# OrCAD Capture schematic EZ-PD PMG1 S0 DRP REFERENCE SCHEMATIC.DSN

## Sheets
1 05. SC8802 REGULATOR: size A3; title: PMG1-S0 DRP REFERENCE DESIGN; rev: 01; note: 630-XXXXX-XX
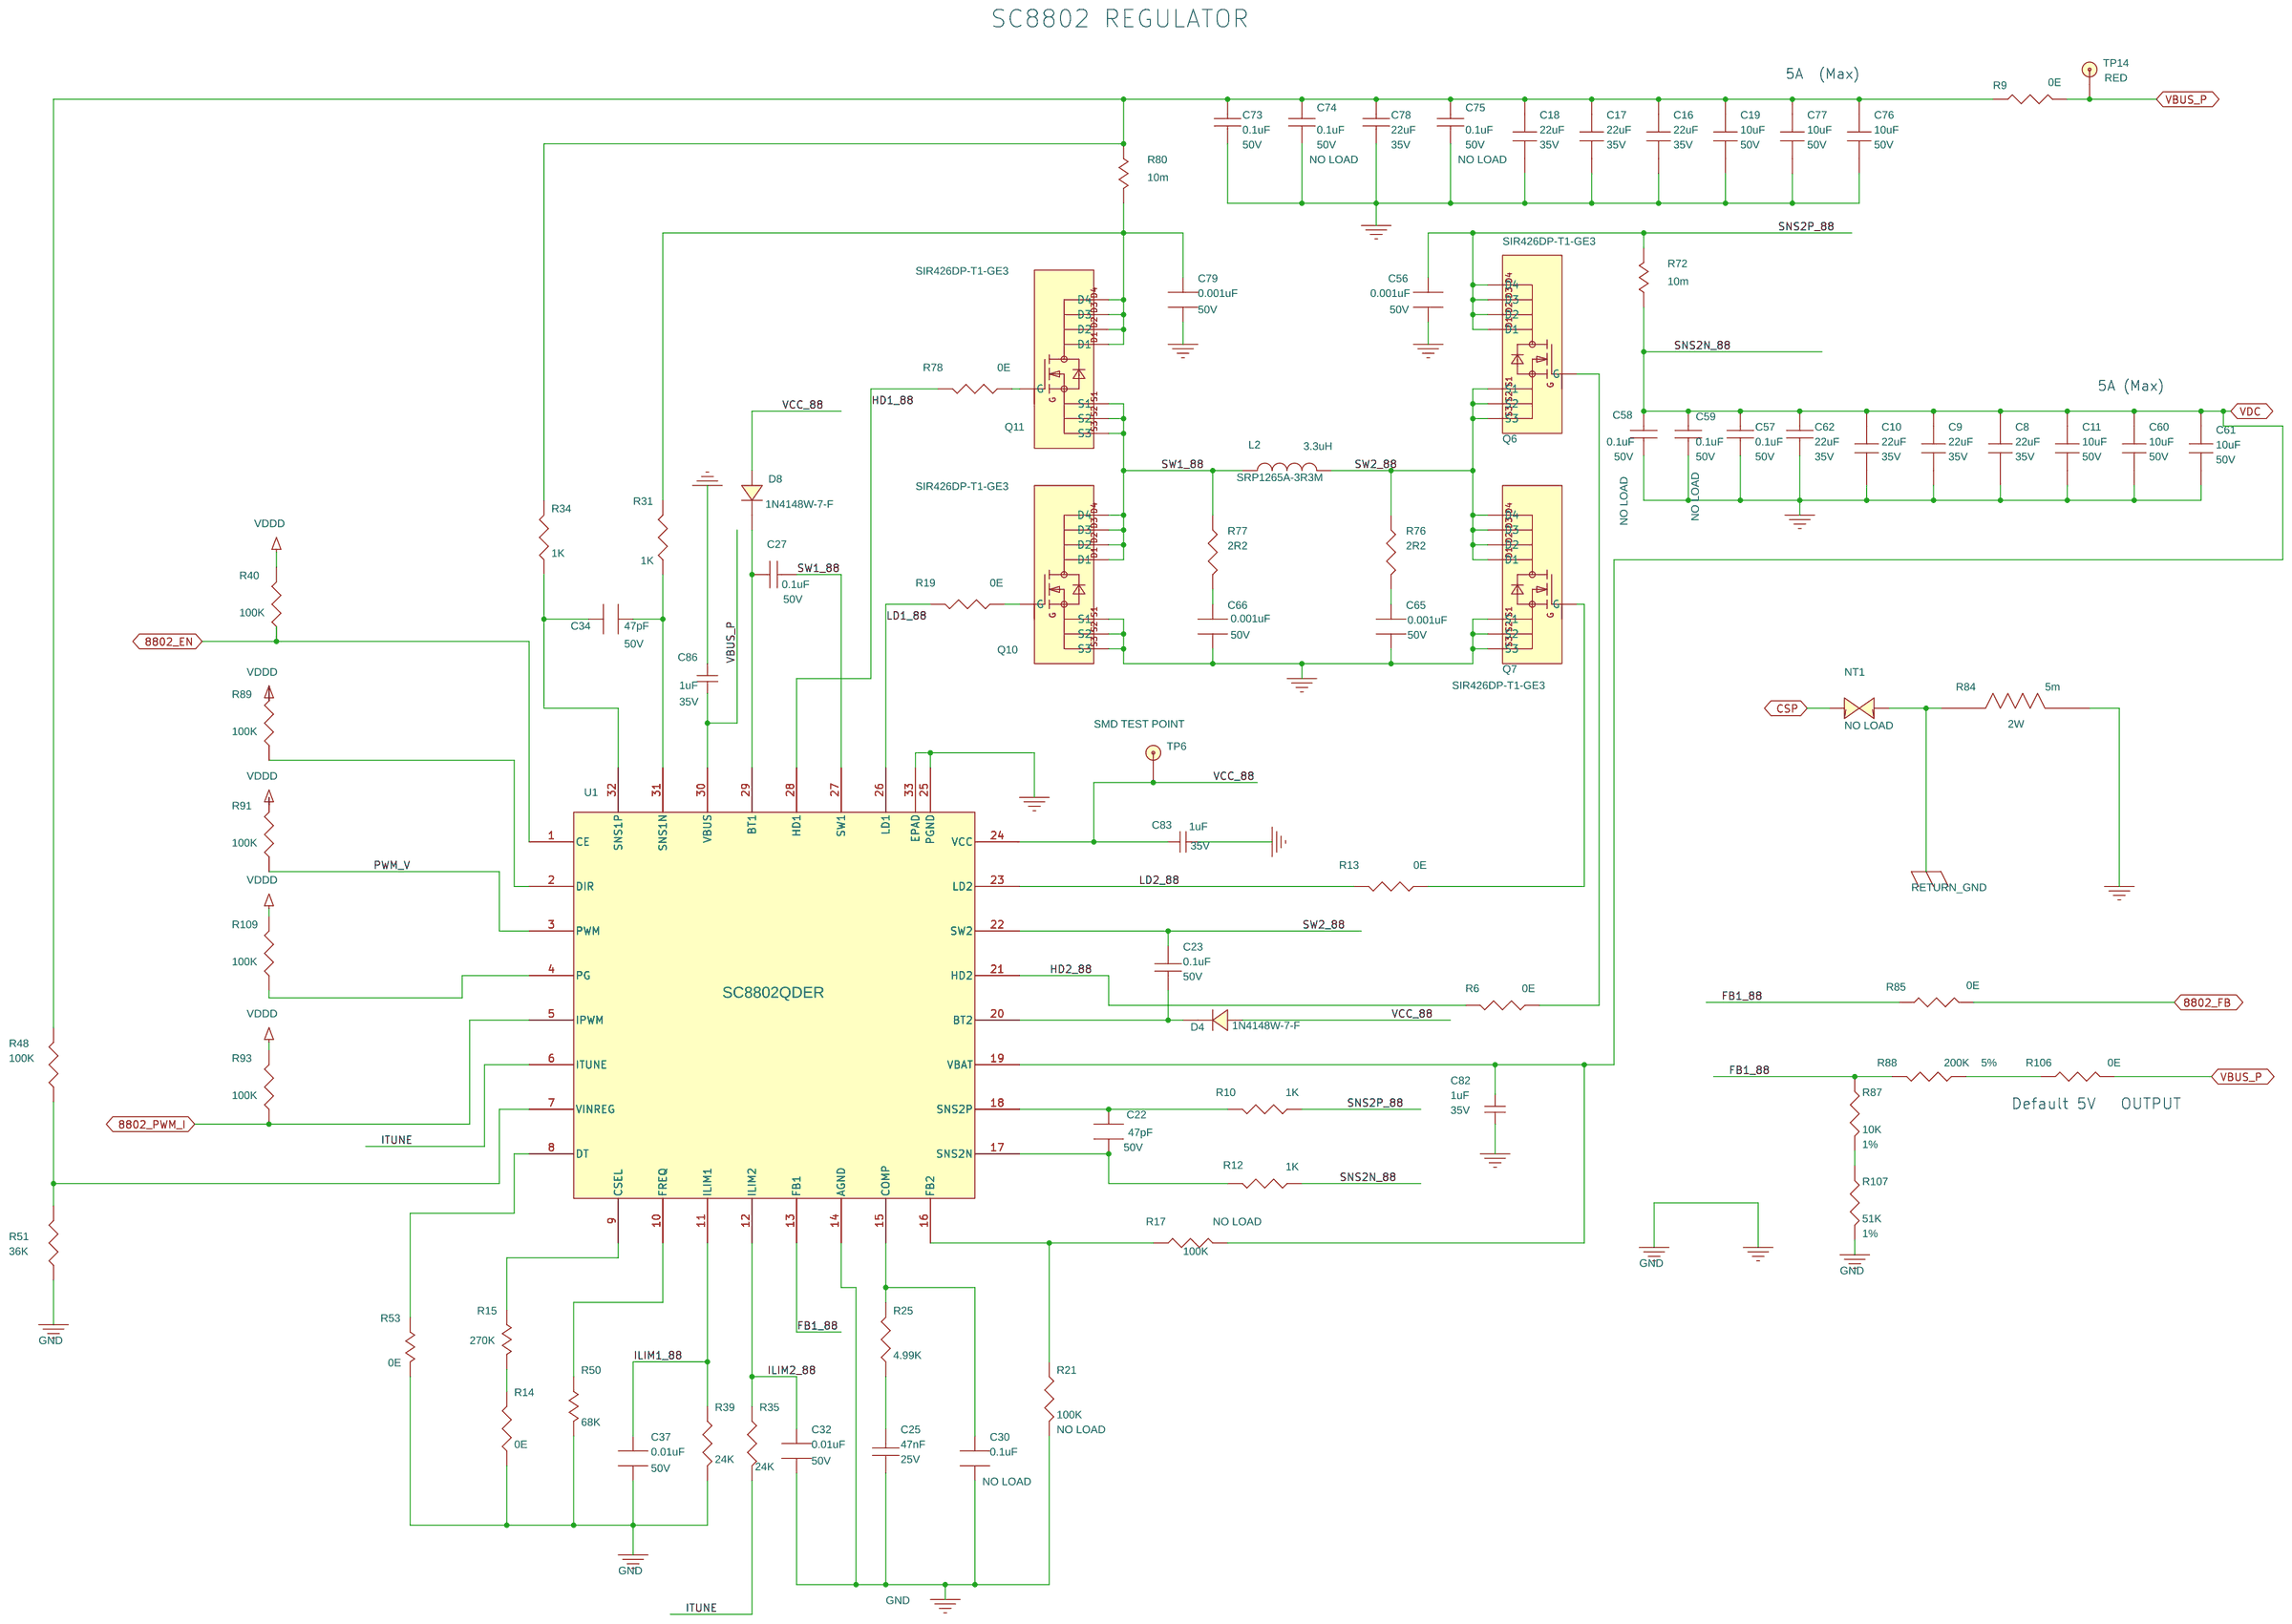
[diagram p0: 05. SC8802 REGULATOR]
2 04. INPUT & STEP DOWN REGULATOR: size A3
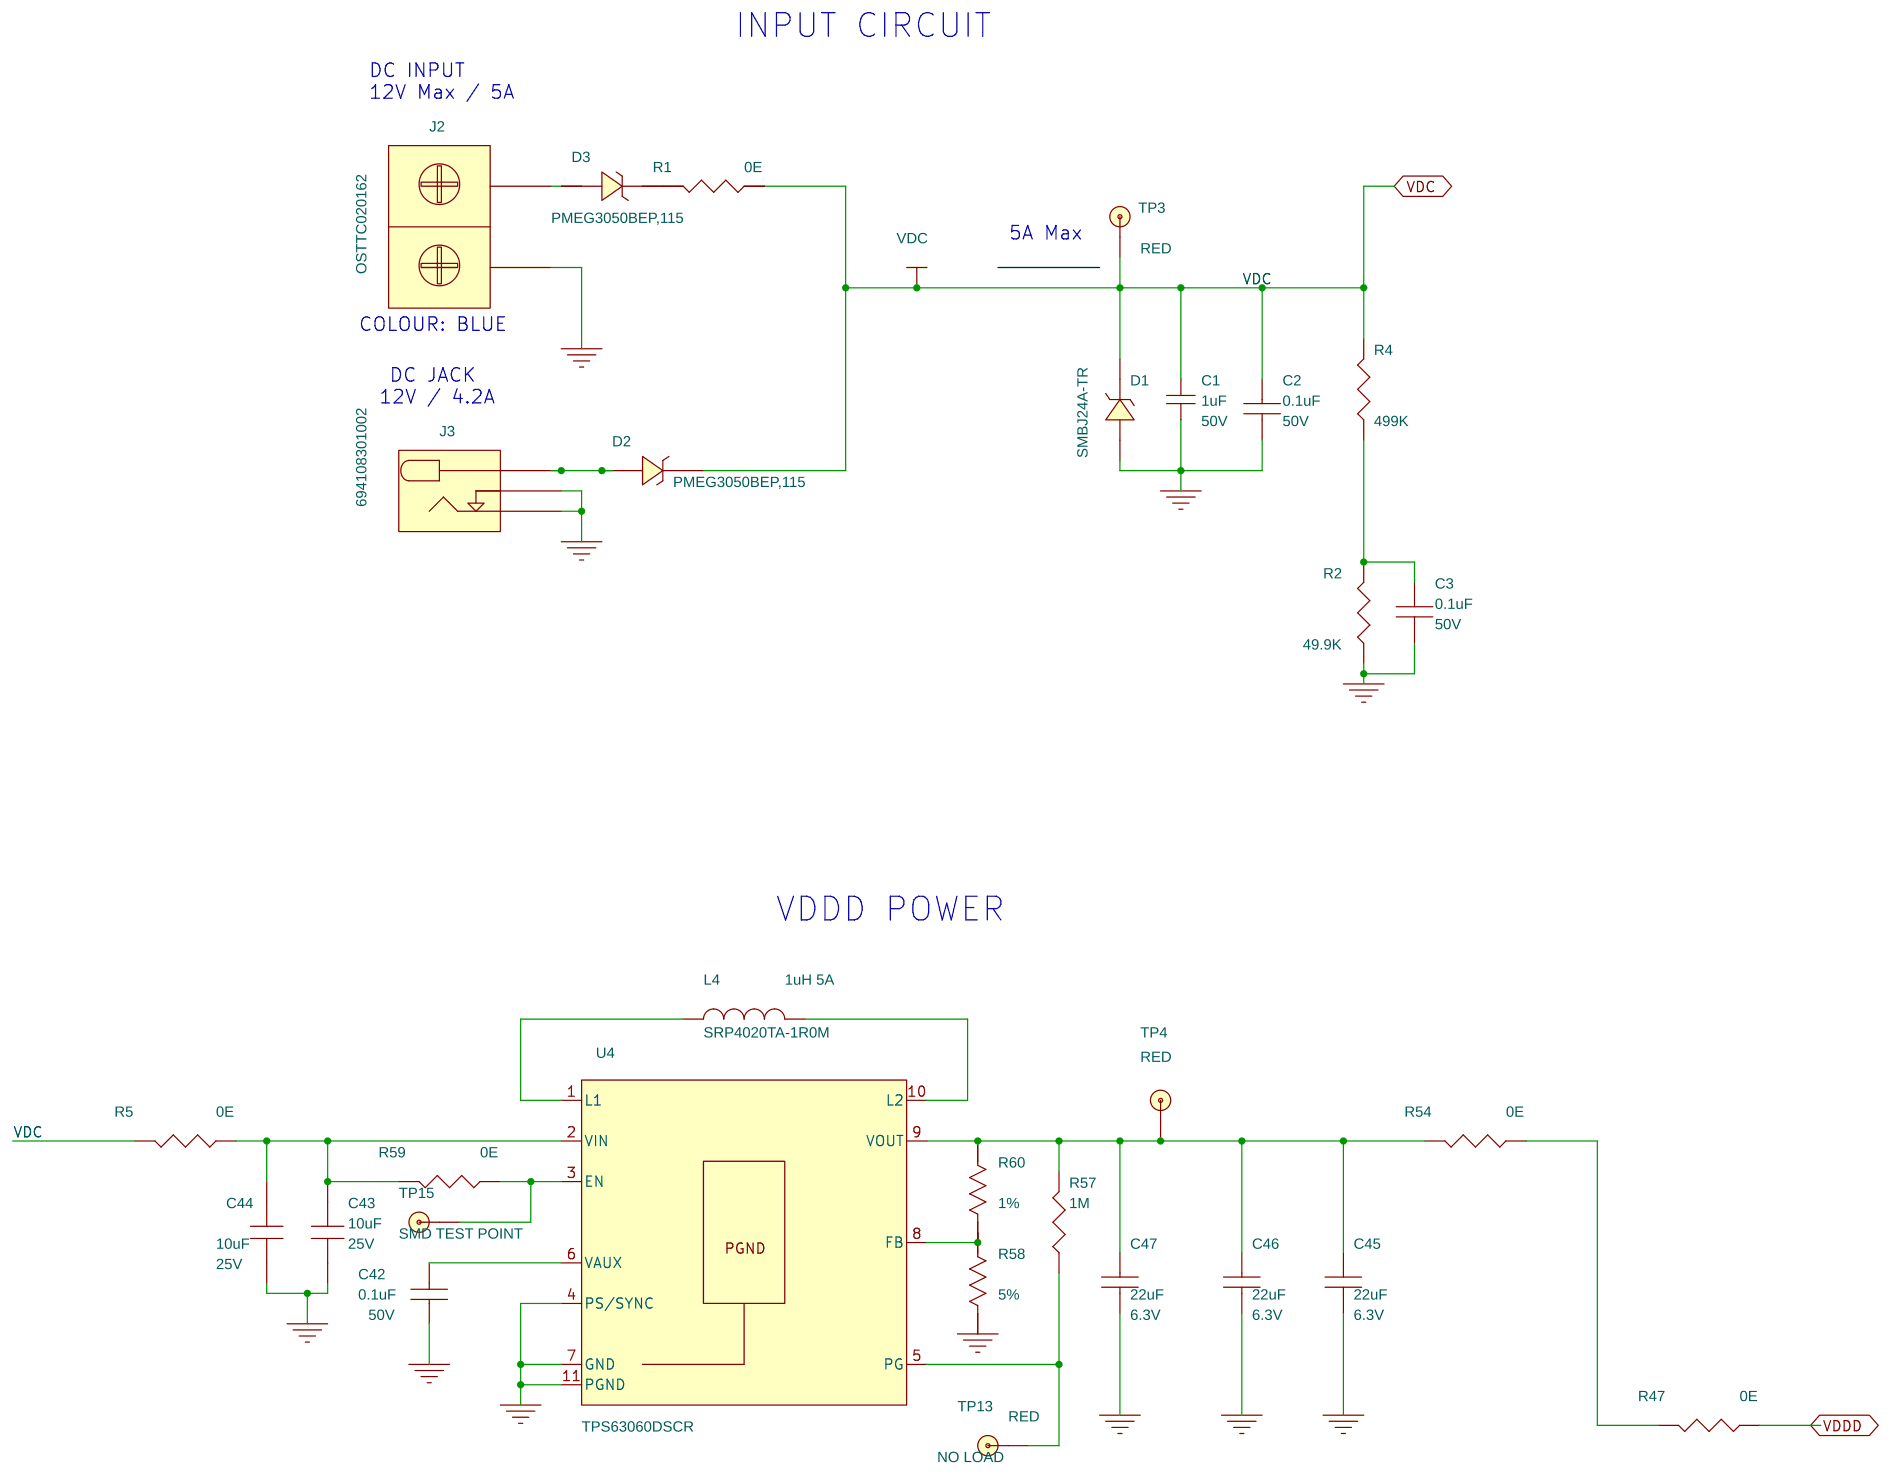
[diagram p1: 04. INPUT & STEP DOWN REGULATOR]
3 06. REVISION HISTORY
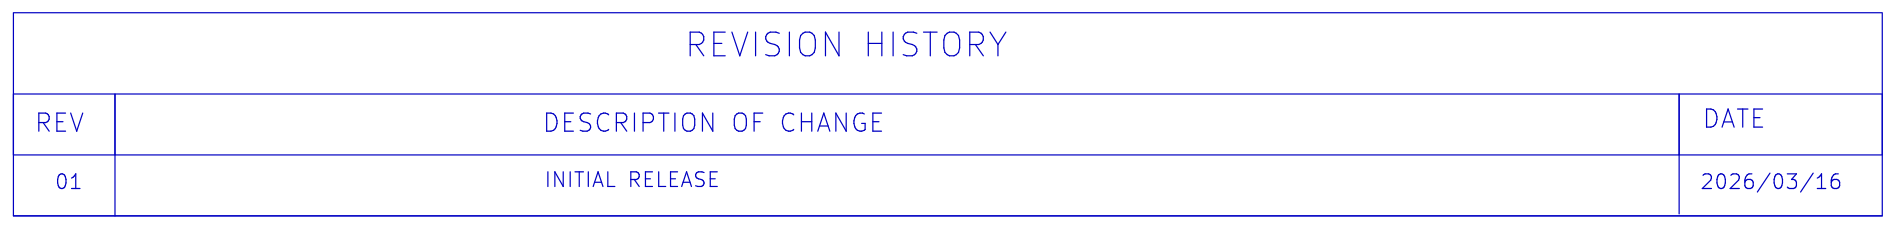
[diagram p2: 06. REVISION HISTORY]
4 01. TITLE PAGE
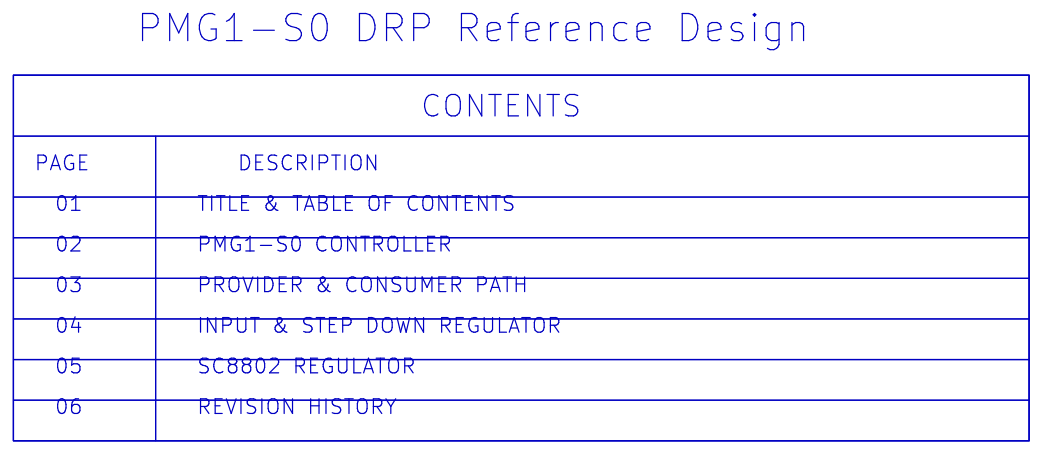
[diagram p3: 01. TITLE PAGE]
5 02. PMG1-S0 CONTROLLER: size A4
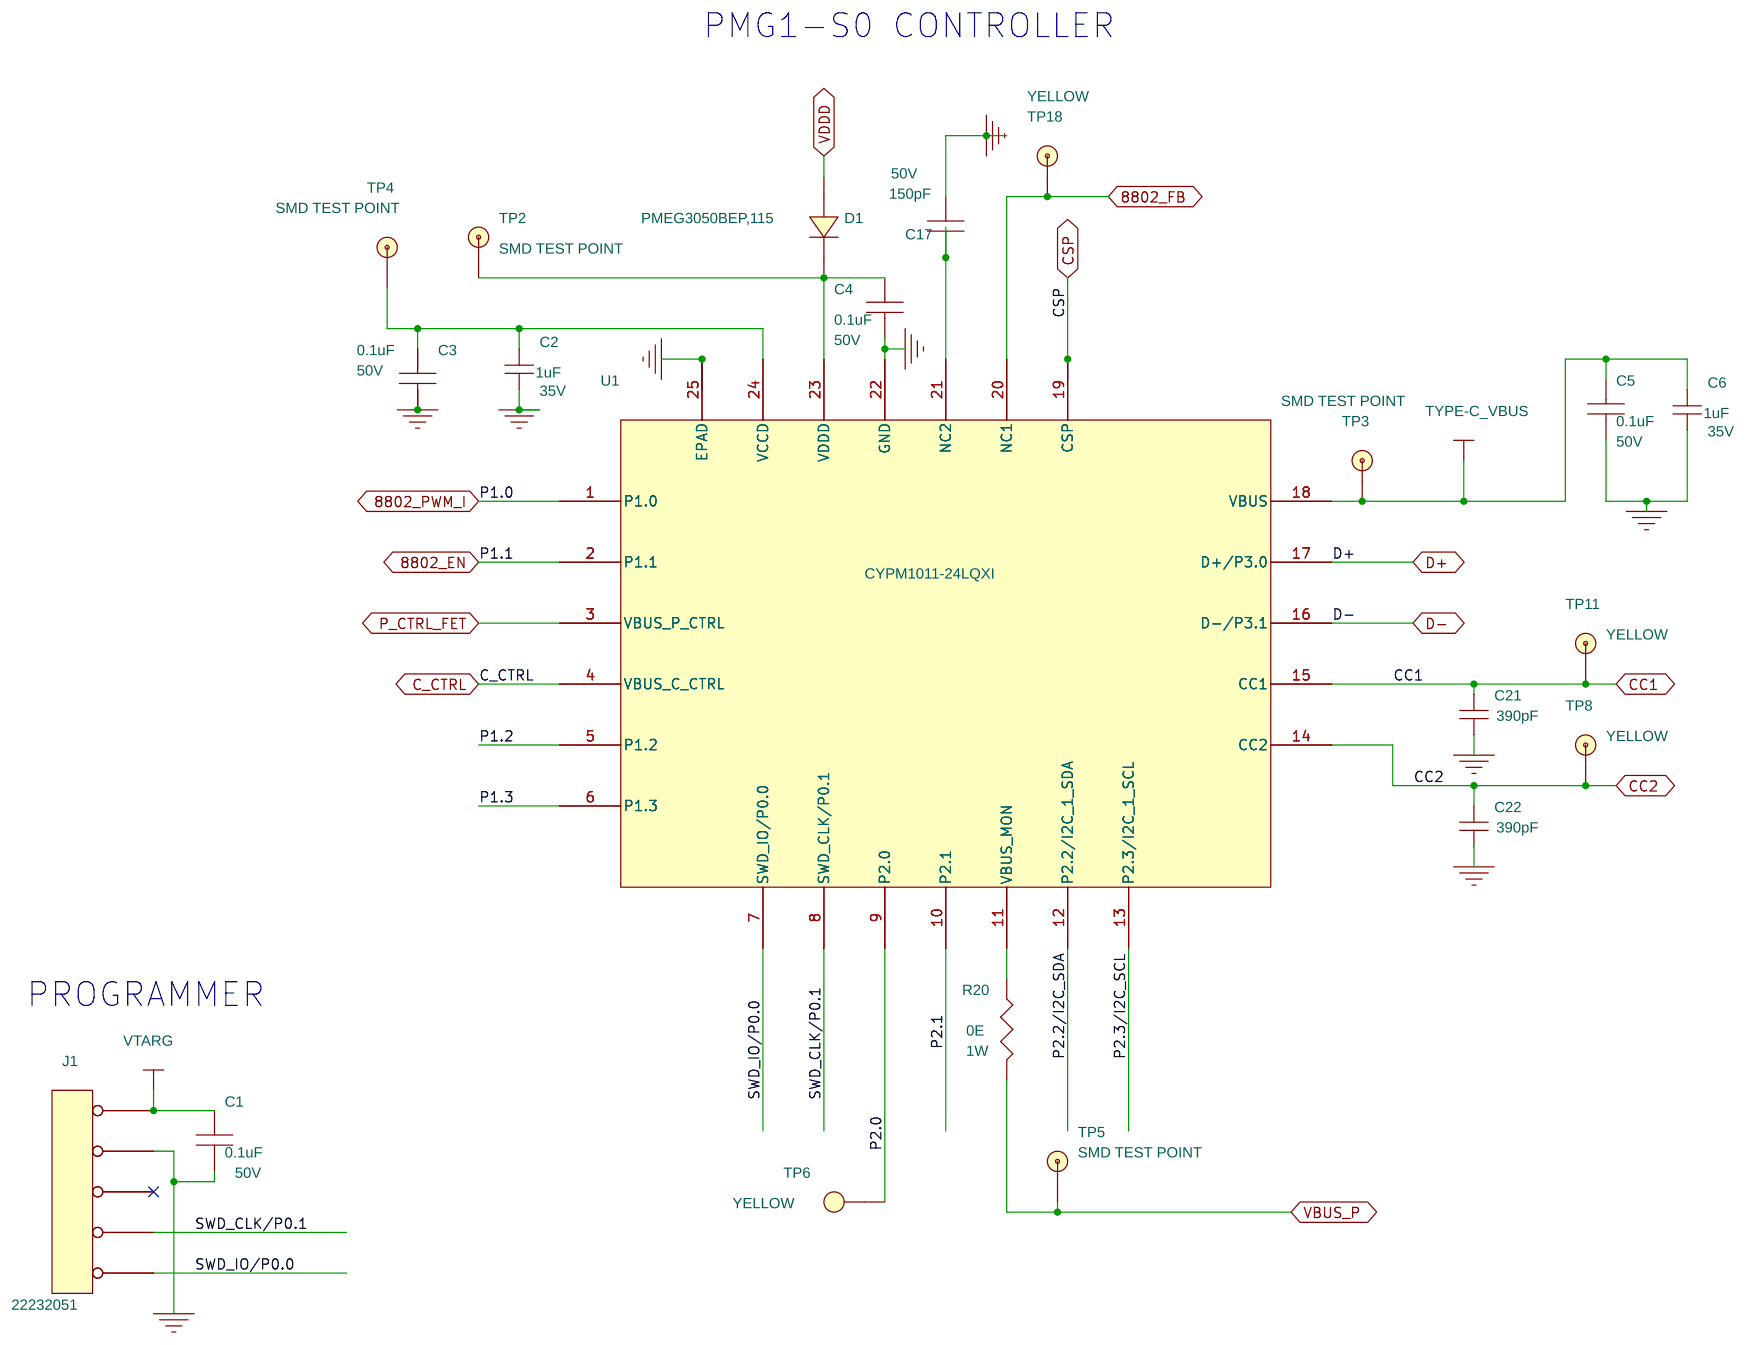
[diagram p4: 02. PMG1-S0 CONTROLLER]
6 03. PROVIDER & CONSUMER PATH: size A4
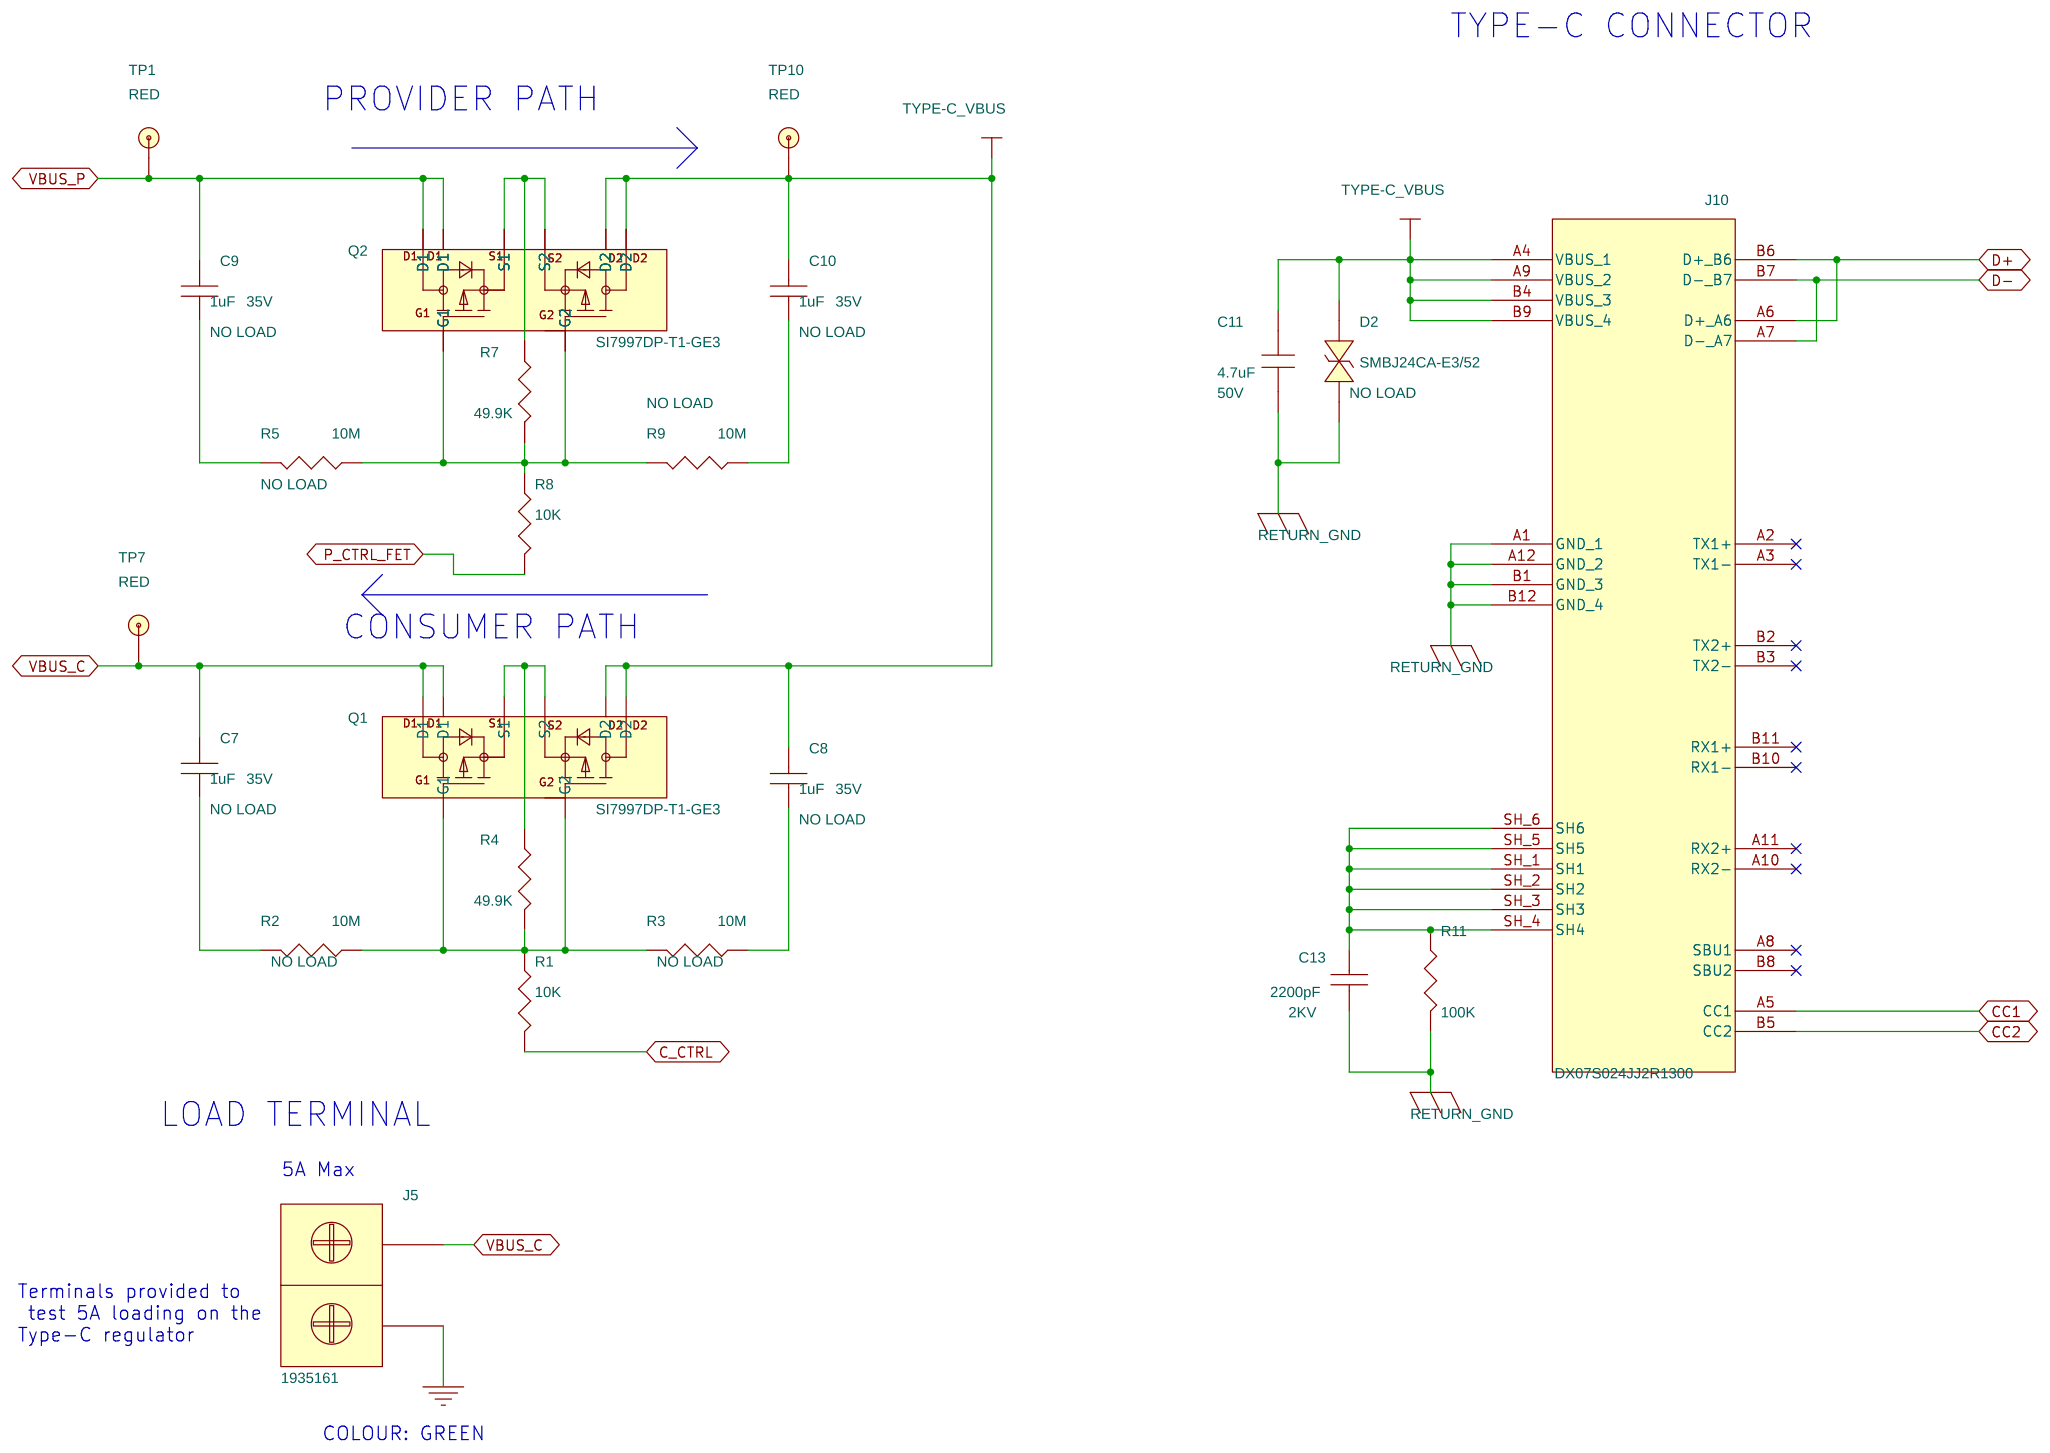
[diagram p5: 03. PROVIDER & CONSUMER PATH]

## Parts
sheet 02. PMG1-S0 CONTROLLER
C1  0.1uF  [capc1005x56n_cyps]
C2  1uF  [capc1005x56n_cyps]
C3  0.1uF  [capc1005x56n_cyps]
C4  0.1uF  [capc1005x56n_cyps]
C5  0.1uF  [capc1005x56n_cyps]
C6  1uF  [capc1005x56n_cyps]
C21  390pF  [capc1005x56n_cyps]
D1  PMEG3050BEP,115  [PMEG3050EP-115]
J1  22232051  [hdr5_keyed_m]
R20  0E  [RESC6330X80N]
TP2  TEST_POINT  [SMD_TEST_POINT]
TP3  TEST_POINT  [SMD_TEST_POINT]
TP4  TEST_POINT  [SMD_TEST_POINT]
TP5  TEST_POINT  [SMD_TEST_POINT]
TP8  YELLOW  [TP-43R_S]
TP11  YELLOW  [TP-43R_S]
TP18  YELLOW  [TP-43R_S]
sheet 03. PROVIDER & CONSUMER PATH
C7  1uF  [capc1005x56n_cyps]
C8  1uF  [capc1005x56n_cyps]
C9  1uF  [capc1005x56n_cyps]
C10  1uF  [capc1005x56n_cyps]
C11  4.7uF  [capc3225x280n_tdk]
C13  2200pF  [C1808]
D2  SMBJ24CA-E3/52  [SMBJ24CA_3P679_2H44]
J5  1935161  [1935161]
J10  DX07S024JJ2R1300  [USB-PD_TYPE-C]
Q1  SI7997DP-T1-GE3  [soic127p600x175-8n_ti]
Q2  SI7997DP-T1-GE3  [soic127p600x175-8n_ti]
R1  10K  [resc1005x40n_pec]
R2  10M  [resc1005x40n_pec]
R3  10M  [resc1005x40n_pec]
R4  49.9K  [resc1005x40n_pec]
R5  10M  [resc1005x40n_pec]
R7  49.9K  [resc1005x40n_pec]
R8  10K  [resc1005x40n_pec]
R9  10M  [resc1005x40n_pec]
R11  100K  [RESC1005X40N_PEC]
TP1  RED  [TP-43R_S]
TP7  RED  [TP-43R_S]
TP10  RED  [TP-43R_S]
sheet 04. INPUT & STEP DOWN REGULATOR
C3#2  0.1uF  [capc1005x56n_cyps]
C42  0.1uF  [capc1005x56n_cyps]
C43  10uF  [CAPC1608X90N_TY]
C44  10uF  [CAPC1608X90N_TY]
C45  22uF  [0402]
C46  22uF  [0402]
C47  22uF  [0402]
D3  PMEG3050BEP,115  [PMEG3050EP-115]
J2  OSTTC020162  [TERMINAL_BLOCK_2PIN]
J3  694108301002  [RAPC712]
L4  1uH 5A  [INDM4440X200N]
R1#2  0E  [RESC1608X55M_A]
R47  0E  [RESC1608X55M_A]
R54  0E  [RESC1608X55M_A]
R57  1M  [resc1005x40n_pec]
R58  110K  [RESC1005X40N_PEC]
R59  0E  [resc1005x40n_pec]
R60  1M  [RESC1005X40N_PEC]
TP3#2  RED  [TP-43R_S]
TP4#2  RED  [TP-43R_S]
TP13  RED  [TP-43R_S]
TP15  TEST_POINT  [SMD_TEST_POINT]
U4  TPS63060DSCR  [WSON50P315X315X80_11T335X170N]
sheet 05. SC8802 REGULATOR
C11#2  10uF  [capc3216x180n_tdk]
C16  22uF  [capc3216x180n_tdk]
C17  22uF  [capc3216x180n_tdk]
C18  22uF  [capc3216x180n_tdk]
C19  10uF  [capc3216x180n_tdk]
C22  47pF  [capc1005x56n_cyps]
C23  0.1uF  [CAPC1608X90N_TY]
C25  47nF  [capc1005x56n_cyps]
C27  0.1uF  [capc1005x56n_cyps]
C30  0.1uF  [capc1005x56n_cyps]
C32  0.01uF  [capc1005x56n_cyps]
C34  47pF  [capc1005x56n_cyps]
C37  0.01uF  [capc1005x56n_cyps]
C56  0.001uF  [capc1608x90n_ty]
C57  0.1uF  [capc1005x56n_cyps]
C58  0.1uF  [capc1005x56n_cyps]
C59  0.1uF  [capc1005x56n_cyps]
C60  10uF  [capc3216x180n_tdk]
C61  10uF  [capc3216x180n_tdk]
C62  22uF  [capc3216x180n_tdk]
C65  0.001uF  [capc1608x90n_ty]
C66  0.001uF  [capc1608x90n_ty]
C73  0.1uF  [capc1005x56n_cyps]
C74  0.1uF  [capc1005x56n_cyps]
C75  0.1uF  [capc1005x56n_cyps]
C76  10uF  [capc3216x180n_tdk]
C77  10uF  [capc3216x180n_tdk]
C78  22uF  [capc3216x180n_tdk]
C79  0.001uF  [capc1608x90n_ty]
C82  1uF  [CAPC1005X56N_CYPS]
C83  1uF  [CAPC1005X56N_CYPS]
C86  1uF  [CAPC1005X56N_CYPS]
D4  1N4148W-7-F  [SOD3715X145N]
D8  1N4148W-7-F  [SOD3715X145N]
L2  3.3uH  [ind_srp1245a]
NT1  Net Tie  [net_tie]
Q6  SIR426DP-T1-GE3  [SOIC127P600X175-8N_TI]
Q7  SIR426DP-T1-GE3  [SOIC127P600X175-8N_TI]
Q10  SIR426DP-T1-GE3  [SOIC127P600X175-8N_TI]
Q11  SIR426DP-T1-GE3  [SOIC127P600X175-8N_TI]
R6  0E  [resc1608x55n_pec]
R10  1K  [resc1005x40n_pec]
R12  1K  [resc1005x40n_pec]
R13  0E  [resc1608x55n_pec]
R14  0E  [RESC1608X55M_A]
R15  270K  [resc1005x40n_pec]
R17  100K  [resc1005x40n_pec]
R19  0E  [resc1608x55n_pec]
R21  100K  [resc1005x40n_pec]
R25  4.99K  [resc1005x40n_pec]
R31  1K  [resc1005x40n_pec]
R34  1K  [resc1005x40n_pec]
R35  24K  [resc1005x40n_pec]
R39  24K  [resc1005x40n_pec]
R40  100K  [RESC1005X40N_PEC]
R48  100K  [RESC1005X40N_PEC]
R50  68K  [resc1005x40n_pec]
R51  36K  [resc1005x40n_pec]
R53  0E  [resc1005x40n_pec]
R72  10m  [resc3216x65n_rohm]
R76  2R2  [resc1608x55n_pec]
R77  2R2  [resc1608x55n_pec]
R78  0E  [resc1608x55n_pec]
R80  10m  [resc3216x65n_rohm]
R84  5m  [RESC6330X80N]
R85  0E  [resc1005x40n_pec]
R87  10K  [resc1005x40n_pec]
R88  200K  [resc1005x40n_pec]
R89  100K  [RESC1005X40N_PEC]
R91  100K  [RESC1005X40N_PEC]
R93  100K  [RESC1005X40N_PEC]
R106  0E  [resc1005x40n_pec]
R107  51K  [resc1005x40n_pec]
R109  100K  [RESC1005X40N_PEC]
TP6  TEST_POINT  [SMD_TEST_POINT]
TP14  RED  [TP-43R_S]
U1  SC8802QDER  [QFN40P400X400X80-33T270X270N]

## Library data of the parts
C1 C3-C5 C27 C42 C57 C73 = CAP_NP: CAP CER 0.1UF 50V X7R 0402; DIGI-KEY PART NO: 445-11261-1-ND; MFG Part number: CGA2B3X7R1H104K050BB; Manufacturer: TDK Corporation; Mfr_Name: TDK Corporation; Mfr_Part#: CGA2B3X7R1H104K050BB; Price: 0.1; Tolerance: 10%; VOLTAGE: 50V
C2 C6 = Cap_1uF_25V_X5R_0402_TDK_0: CAP CER 1UF 35V X5R 0402; MFG Part number: CL05A105KL5NRNC; Manufacturer: Samsung Electro-Mechanics America, Inc.; Manufacturer Part Number: UMK107AB7105KA-T; Mfr_Name: Samsung Electro-Mechanics America, Inc.; Mfr_Part#: CL05A105KL5NRNC; Voltage: 35V
C21 = Cap_390pF_50V_X7R_0402_AVX_0: CAP CER 390PF 50V C0G/NP0 0402; MFG Part number: GRM1555C1H391JA01J; Manufacturer: Murata Electronics North America; Mfr_Name: Murata Electronics North America; Mfr_Part#: GRM1555C1H391JA01J
D1 = DIODE: DIODE SCHOTTKY 30V 5A SOD128; Manufacturer: Nexperia USA Inc.; Mfr_Name: Nexperia USA Inc.
J1 = CON5_0: CONN HEADER 5POS .100 VERT TIN; DIGI-KEY PART NO: WM4203-ND; Manufacturer: Molex, LLC; Mfr_Name: Molex, LLC; Price: 0.35
R20 = RESISTOR_v2: RES SMD 0.0 OHM JUMPER 1W 2512; MFG Part number: RMCF2512ZT0R00; Manufacturer: Stackpole Electronics Inc.; Mfr_Name: Stackpole Electronics Inc.; Mfr_Part#: RMCF2512ZT0R00; Part Number: HCJ0603; TOLERANCE: 1%; WATT: 1W
TP2-TP6 TP15 = TEST_POINT: SMD TEST POINT; Asm_Instruction: NO LOAD; Price: 0.36
TP8 TP11 TP18 = TEST_POINT: TEST POINT PC MINI .040"D YELLOW; DIGI-KEY PART NO: 36-5004-ND; MFG Part number: 5004; Manufacturer: Keystone Electronics; Mfr_Name: Keystone Electronics; Mfr_Part#: 5004; Price: 0.36
C7-C10 = CAP_NP: CAP CER 1UF 35V X5R 0402; Asm_Instruction: NO LOAD; DIGI-KEY PART NO: 445-9073-1-ND; MFG Part number: CL05A105KL5NRNC; Manufacturer: Samsung Electro-Mechanics America, Inc.; Mfr_Name: Samsung Electro-Mechanics America, Inc.; Mfr_Part#: CL05A105KL5NRNC; Price: 0.18; Voltage: 35V
C11 = 10uF-50V-10%-X5R-1206: CAP CER 4.7UF 50V X7R 1210; Cypress Part No: 510-60425-01; DIGI-KEY PART NO: 1276-1292-1-ND; MFG Part number: CL32B475KBUYNNE; Manufacturer: Samsung Electro-Mechanics America, Inc.; Mfr_Name: Samsung Electro-Mechanics America, Inc.; Mfr_Part#: CL32B475KBUYNNE; Price: 0.47; Voltage: 50V
C13 = CAP_NP: CAP CER 2200PF 2KV 10% X7R 1808; DIGI-KEY PART NO: 709-1306-1-ND; MFG Part number: 202R29W222KV4E; Manufacturer: Johanson Dielectrics Inc; Mfr_Name: Johanson Dielectrics Inc; Mfr_Part#: 202R29W222KV4E; Price: 0.49; Tolerance: 10%; VOLTAGE: 2KV
D2 = BZX84C18_SOT_1: TVS DIODE 24VWM 38.9VC SMB; Asm_Instruction: NO LOAD; Cypress Part No: 530-60094-01; DIGI-KEY PART NO: SMBJ24CA-E3/52GICT-ND; Manufacturer: Vishay Semiconductor Diodes Division; Mfr_Name: Vishay Semiconductor Diodes Division; Price: 0.41
J5 = TERMINAL_BLOCK: TERM BLOCK PCB 2POS 5.0MM GREEN; DIGI-KEY PART NO: 277-1667-ND; Manufacturer: Phoenix Contact; Mfr_Name: Phoenix Contact; Price: 0.39
J10 = USB-PD_TYPE-C_20: CONN RCPT USB3.1 TYPEC SMD R/A; DIGI-KEY PART NO: 670-2794-1-ND; Manufacturer: JAE Electronics; Mfr_Name: JAE Electronics; Price: 2.61
Q1 Q2 = MOSFET_N_GDS_10: MOSFET 2P-CH 30V 60A PPAK SO-8; DIGI-KEY PART NO: SI7997DP-T1-GE3CT-ND; Manufacturer: Vishay Siliconix; Mfr_Name: Vishay Siliconix; Price: 2.16
R1 R8 = RESISTOR_v2: RES SMD 10K OHM 1% 1/16W 0402; DIGI-KEY PART NO: 1276-3431-1-ND; MFG Part number: RC0402FR-0710KL; Manufacturer: Yageo; Mfr_Name: Yageo; Mfr_Part#: RC0402FR-0710KL; Price: 0.1; TOLERANCE: 1%
R2 R3 R5 R9 = R: RES SMD 10M OHM 5% 1/16W 0402; Asm_Instruction: NO LOAD; DIGI-KEY PART NO: RHM10MBICT-ND; MFG Part number: RC0402JR-0710ML; Manufacturer: Yageo; Mfr_Name: Yageo; Mfr_Part#: RC0402JR-0710ML; Price: 0.11; Tolerance: 5%
R4 R7 = R: RES SMD 49.9K OHM 1% 1/5W 0402; DIGI-KEY PART NO: P49.9KLCT-ND; MFG Part number: RCS040249K9FKED; Manufacturer: Vishay Dale; Mfr_Name: Vishay Dale; Mfr_Part#: RCS040249K9FKED; Price: 0.1; Tolerance: 1%
R11 = R: RES SMD 100K OHM 1% 1/16W 0402; MFG Part number: RC0402FR-07100KL; Manufacturer: Yageo; Mfr_Name: Yageo; Mfr_Part#: RC0402FR-07100KL
TP1 TP7 TP10 TP14 = TEST_POINT: TEST POINT PC MINI .040"D RED; DIGI-KEY PART NO: 36-5000-ND; MFG Part number: 5000; Manufacturer: Keystone Electronics; Mfr_Name: Keystone Electronics; Mfr_Part#: 5000; Price: 0.36
C3#2 = CAP_NP: CAP CER 0.1UF 50V X7R 0402; DIGI-KEY PART NO: 445-11261-1-ND; MFG Part number: CGA2B3X7R1H104K050BB; Manufacturer: TDK Corporation; Mfr_Name: TDK Corporation; Mfr_Part#: CGA2B3X7R1H104K050BB; Price: 0.1; Tolerance: 10%; VOLTAGE: 50V
C43 C44 = 10uF-50V-10%-X5R-1206: CAP CER 10UF 25V X5R 0603; MFG Part number: GRM188R61E106MA73D; Manufacturer: Murata Electronics North America; Mfr_Name: Murata Electronics North America; Mfr_Part#: GRM188R61E106MA73D; PART_NUMBER: C3216X5R1H106K160AB; Voltage: 25V
C45-C47 = CAPACITOR_NON-POL: CAP CER 22UF 6.3V X5R 0603; ALTERNATE PART NUMBER: CL10A226MQ8NRNC; Alternate Manufacturer: Samsung Electro-Mechanics; MFG Part number: GRM188R60J226MEA0D; Manufacturer: Murata Electronics North America; Mfr_Name: Murata Electronics North America; Mfr_Part#: GRM188R60J226MEA0D; Part_Number: GRM188R60J106ME47D; Tolerance: 20%; VOLTAGE: 6.3V; mfg: GRM188R60J106KME84D, Murata
D3 = BZX84C18_SOT_0: DIODE SCHOTTKY 30V 5A SOD128; DIGI-KEY PART NO: 568-6519-1-ND; Manufacturer: Nexperia USA Inc; Mfr_Name: Nexperia USA Inc; Price: 0.48
J2 = TERMINAL_BLOCK: TERMINAL BLOCK 5MM VERT 2POS PCB; DIGI-KEY PART NO: ED2600-ND; Manufacturer: On Shore Technology Inc.; Mfr_Name: On Shore Technology Inc.; Price: 0.46
J3 = CONN_JACK_PWR_2: CONN PWR JACK 2.5X5.5MM SOLDER; DIGI-KEY PART NO: 732-5934-ND; Manufacturer: Wurth Electronics Inc; Mfr_Name: Wurth Electronics Inc
L4 = INDUCTOR: FIXED IND 1UH 5A 27 MOHM SMD; Lead Free: YES; MFG Part number: SRP4020TA-1R0M; Manufacturer: Bourns Inc.; Mfr_Name: Bourns Inc.; Mfr_Part#: SRP4020TA-1R0M; PART_NUMBER: 74438324010; Part Number: 74438324010; mfg: Coilcraft, XFL4020-102MEB
R1#2 = RESISTOR_v2: RES SMD 0 OHM JUMPER 1/10W 0603; Asm_Instruction: NO LOAD; DIGI-KEY PART NO: RHM.010AUCT-ND; MFG Part number: RC0603JR-070RL; Manufacturer: Yageo; Mfr_Name: Yageo; Mfr_Part#: RC0603JR-070RL; Part Number: HCJ0603; Price: 0.77; TOLERANCE: 1%; WATT: 0.25W
R47 R54 = RESISTOR_v2: RES SMD 0 OHM JUMPER 1/10W 0603; MFG Part number: RC0603JR-070RL; Manufacturer: Yageo; Mfr_Name: Yageo; Mfr_Part#: RC0603JR-070RL; Part Number: HCJ0603; TOLERANCE: 1%; WATT: 0.25W
R57 = 5.49K-1_10W-1%-0603: RES SMD 1M OHM 1% 1/16W 0402; Dist1_PN: P1.00KHTR-ND; MFG Part number: RC0402FR-071ML; Manufacturer: Yageo; Mfg1_PN: ERJ-3EKF1001V; Mfr_Name: Yageo; Mfr_Part#: RC0402FR-071ML; PART_NUMBER: ERJ-3EKF1001V
R58 = RESISTOR: RES SMD 110K OHM 5% 1/16W 0402; MFG Part number: RC0402JR-07110KL; Manufacturer: Yageo; Mfr_Name: Yageo; Mfr_Part#: RC0402JR-07110KL; PART_NUMBER: ERJ-2RKF5112X; Tolerance: 5%
R59 = RESISTOR_v2: RES SMD 0 OHM JUMPER 1/10W 0402; ALTERNATE PART NUMBER: ERJ-2GE0R00X; Alternate Manufacturer: Panasonic Electronic Components; Alternate Mfr Part #: RC0402JR-070RL; MFG Part number: MCS04020Z0000ZE000; Manufacturer: Vishay Beyschlag; Mfr_Name: Vishay Beyschlag; Mfr_Part#: MCS04020Z0000ZE000; Part Number: HCJ0603; TOLERANCE: 1%; WATT: 0.25W
R60 = RESISTOR: RES SMD 1M OHM 1% 1/16W 0402; MFG Part number: RC0402FR-071ML; Manufacturer: Yageo; Mfr_Name: Yageo; Mfr_Part#: RC0402FR-071ML; PART_NUMBER: ERJ-2RKF4703X; Tolerance: 1%
TP3#2 TP4#2 = TEST_POINT: TEST POINT PC MINI .040"D RED; DIGI-KEY PART NO: 36-5000-ND; MFG Part number: 5000; Manufacturer: Keystone Electronics; Mfr_Name: Keystone Electronics; Mfr_Part#: 5000; Price: 0.36
TP13 = TEST_POINT: TEST POINT PC MINI .040"D RED; Asm_Instruction: NO LOAD; DIGI-KEY PART NO: 36-5000-ND; MFG Part number: 5000; Manufacturer: Keystone Electronics; Mfr_Name: Keystone Electronics; Mfr_Part#: 5000; Price: 0.36
U4 = AOZ1050PI_3: IC REG BUCK BOOST ADJ 2A 10WSON; Manufacturer: Texas Instruments; Mfr_Name: Texas Instruments; PART_NUMBER: TPS63036YFGR
C11#2 = 10uF-50V-10%-X5R-1206: CAP CER 10UF 50V X5R 1206; ALTERNATE PART NUMBER: CL31A106MBHNNNE; Alternate Manufacturer: Samsung Electro-Mechanics; DIGI-KEY PART NO: 490-10756-1-ND; MFG Part number: GRM31CR61H106MA12L; Manufacturer: Murata Electronics North America; Mfr_Name: Murata Electronics North America; Mfr_Part#: GRM31CR61H106MA12L; PART_NUMBER: C3216X5R1H106K160AB; Price: 0.40; Voltage: 50V
C16-C18 = 10uF-50V-10%-X5R-1206: CAP CER 22UF 35V JB 1206; DIGI-KEY PART NO: 445-11739-2-ND; MFG Part number: C3216JB1V226M160AC; Manufacturer: TDK Corporation; Mfr_Name: TDK Corporation; Mfr_Part#: C3216JB1V226M160AC; PART_NUMBER: C3216X5R1H106K160AB; Price: 1.24; Voltage: 35V
C19 C60 C61 C76 C77 = 10uF-50V-10%-X5R-1206: CAP CER 10UF 50V X5R 1206; ALTERNATE PART NUMBER: CL31A106MBHNNNE; Alternate Manufacturer: Samsung Electro-Mechanics; DIGI-KEY PART NO: 490-10756-1-ND; MFG Part number: GRM31CR61H106MA12L; Manufacturer: Murata Electronics North America; Mfr_Name: Murata Electronics North America; Mfr_Part#: GRM31CR61H106MA12L; PART_NUMBER: C3216X5R1H106K160AB; Price: 0.40; Voltage: 50V
C22 C34 = Capacitor_402_Generic_SMD: CAP CER 47PF 50V C0G/NP0 0402; MFG Part number: GRM1555C1H470JA01D; Manufacturer: Murata Electronics North America; Mfr_Name: Murata Electronics North America; Mfr_Part#: GRM1555C1H470JA01D; Voltage: 50V
C23 = CAP_NP: CAP CER 0.1UF 50V X7R 0603; DIGI-KEY PART NO: 399-7845-1-ND; MFG Part number: C0603C104M5RACTU; Manufacturer: Kemet; Mfr_Name: Kemet; Mfr_Part#: C0603C104M5RACTU; Price: 0.10; Tolerance: 10%; VOLTAGE: 50V
C25 = CAP_NP: CAP CER 0.047UF 25V X5R 0402; MFG Part number: CGA2B2X5R1E473M050BA; Manufacturer: TDK Corporation; Mfr_Name: TDK Corporation; Mfr_Part#: CGA2B2X5R1E473M050BA; PART_NUMBER: C1005X5R1E223K050BA; PCB Assembly: Y; Part Number: C0603X5R1E223K030BB; Voltage: 25V
C30 = Capacitor_402_Generic_SMD: CAP CER 0.1UF 50V X7R 0402; Asm_Instruction: NO LOAD; DIGI-KEY PART NO: 445-11261-1-ND; MFG Part number: CGA2B3X7R1H104K050BB; Manufacturer: TDK Corporation; Mfr_Name: TDK Corporation; Mfr_Part#: CGA2B3X7R1H104K050BB; Price: 0.1; Voltage: 50V
C32 C37 = Capacitor_402_Generic_SMD: CAP CER 10000PF 50V X7R 0402; MFG Part number: 04025C103KAT2A; Manufacturer: AVX Corporation; Mfr_Name: AVX Corporation; Mfr_Part#: 04025C103KAT2A; Voltage: 50V
C56 C65 C66 C79 = Capacitor_402_Generic_SMD: CAP CER 1000PF 50V X7R 0603; MFG Part number: GRM188R71H102KA01D; Manufacturer: Murata Electronics North America; Mfr_Name: Murata Electronics North America; Mfr_Part#: GRM188R71H102KA01D; Voltage: 50V
C58 = CAP_NP: CAP CER 0.1UF 50V X7R 0402; Asm_Instruction: NO LOAD; DIGI-KEY PART NO: 445-11261-1-ND; MFG Part number: CGA2B3X7R1H104K050BB; Manufacturer: TDK Corporation; Manufacturer's Part Number: C0402C104K8RACTU; Mfr_Name: TDK Corporation; Mfr_Part#: CGA2B3X7R1H104K050BB; PART_NUMBER: C1005X7R1E104K050BB; Part Number: CDN-CAP-2013; Part Type: CAP; Price: 0.1; VOLTAGE: 50V
C59 C74 C75 = CAP_NP: CAP CER 0.1UF 50V X7R 0402; Asm_Instruction: NO LOAD; DIGI-KEY PART NO: 445-11261-1-ND; MFG Part number: CGA2B3X7R1H104K050BB; Manufacturer: TDK Corporation; Mfr_Name: TDK Corporation; Mfr_Part#: CGA2B3X7R1H104K050BB; PART_NUMBER: C1005X5R1E223K050BA; PCB Assembly: Y; Part Number: C0603X5R1E223K030BB; Price: 0.1; Voltage: 50V
C62 C78 = CAP_NP: CAP CER 22UF 35V JB 1206; DIGI-KEY PART NO: 445-11739-2-ND; MFG Part number: C3216JB1V226M160AC; Manufacturer: TDK Corporation; Mfr_Name: TDK Corporation; Mfr_Part#: C3216JB1V226M160AC; PART_NUMBER: C1005X5R1E223K050BA; PCB Assembly: Y; Part Number: C0603X5R1E223K030BB; Price: 1.24; Voltage: 35V
C82 C83 C86 = Cap_1uF_25V_X5R_0402_TDK_0: CAP CER 1UF 35V X5R 0402; DIGI-KEY PART NO: 445-9073-1-ND; MFG Part number: CL05A105KL5NRNC; Manufacturer: Samsung Electro-Mechanics America, Inc.; Manufacturer Part Number: UMK107AB7105KA-T; Mfr_Name: Samsung Electro-Mechanics America, Inc.; Mfr_Part#: CL05A105KL5NRNC; Price: 0.18; Voltage: 35V
D4 D8 = Diode_-_SMA403D_0: DIODE GEN PURP 100V 300MA SOD123; Manufacturer: Diodes Incorporated; Mfr_Name: Diodes Incorporated
L2 = Ind_Wurth_0: FIXED IND 3.3UH 18A 6.8 MOHM SMD; DCR: 6.8 MOHM; DIGI-KEY PART NO: SRP1265A-3R3MCT-ND; Imax: 18A; MFG Part number: SRP1265A-3R3M; Manufacture: Bourns Inc.; Manufacture PN: SRP1265A-3R3M; Manufacturer: Bourns Inc.; Mfr_Name: Bourns Inc.; Mfr_Part#: SRP1265A-3R3M; Price: 1.31
NT1 = Net_Tie: Asm_Instruction: NO LOAD; Package: 5mil; Part Type: Surface Mount
Q6 Q7 Q10 Q11 = SI4172DY-T1-GE3: MOSFET N-CH 40V 30A PPAK SO-8; ALTERNATE PART NUMBER: SI7848BDP-T1-GE3; ALTERNATE PARTNUMBER 1: SIR422DP-T1-GE3; Alternate Manufacturer: Vishay Siliconix; Alternate Mfr Part #: SIR422DP-T1-GE3; DIGI-KEY PART NO: SIR426DP-T1-GE3CT-ND; Manufacturer: Vishay Siliconix; Mfr_Name: Vishay Siliconix; Price: 1.02
R6 R13 R14 R19 R78 = RESISTOR_v2: RES SMD 0 OHM JUMPER 1/10W 0603; DIGI-KEY PART NO: RHM.010AUCT-ND; MFG Part number: RC0603JR-070RL; Manufacturer: Yageo; Mfr_Name: Yageo; Mfr_Part#: RC0603JR-070RL; Part Number: HCJ0603; Price: 0.77; TOLERANCE: 1%; WATT: 0.25W
R10 R12 R31 R34 = 5.49K-1_10W-1%-0603: RES SMD 1K OHM 5% 1/10W 0402; Alternate Manufacturer: Yageo; Alternate Mfr Part #: RC0402JR-071KL; Dist1_PN: P1.00KHTR-ND; MFG Part number: ERJ-2GEJ102X; Manufacturer: Panasonic Electronic Components; Mfg1_PN: ERJ-3EKF1001V; Mfr_Name: Panasonic Electronic Components; Mfr_Part#: ERJ-2GEJ102X; PART_NUMBER: ERJ-3EKF1001V
R15 = Resistor_402_Generic_SMD: RES SMD 270K OHM 1% 1/16W 0402; MFG: Yageo; MFG Part number: RC0402FR-07270KL; Manufacturer: Yageo; Mfr_Name: Yageo; Mfr_Part#: RC0402FR-07270KL
R17 R21 = 330_ohm_5%_0805_0: RES SMD 100K OHM 1% 1/16W 0402; Alternate Mfr Part #: RC0402JR-070RL; Asm_Instruction: NO LOAD; MFG Part number: RC0402FR-07100KL; Manufacturer: Yageo; Mfr_Name: Yageo; Mfr_Part#: RC0402FR-07100KL
R25 = R: RES SMD 4.99K OHM 1% 1/16W 0402; MFG Part number: RMCF0402FT4K99; Manufacturer: Stackpole Electronics Inc.; Manufacturer's Part Number: ERJ-2GEJ103X; Mfr_Name: Stackpole Electronics Inc.; Mfr_Part#: RMCF0402FT4K99; PART_NUMBER: RC0603JR-0710KL; Part Number: CDN-RES-2123; Tolerance: 0.05
R35 R39 = 330_ohm_5%_0805_0: RES SMD 24K OHM 1% 1/16W 0402; MFG Part number: RC0402FR-0724KL; Manufacturer: Yageo; Mfr_Name: Yageo; Mfr_Part#: RC0402FR-0724KL
R40 R89 R91 R93 R109 = R: RES SMD 100K OHM 1% 1/16W 0402; MFG Part number: RC0402FR-07100KL; Manufacturer: Yageo; Mfr_Name: Yageo; Mfr_Part#: RC0402FR-07100KL; Part No.: ERJ-1GEF4322C
R48 = 330_ohm_5%_0805_0: RES SMD 100K OHM 1% 1/16W 0402; MFG Part number: RC0402FR-07100KL; Manufacturer: Yageo; Mfr_Name: Yageo; Mfr_Part#: RC0402FR-07100KL
R50 = Resistor_402_Generic_SMD: RES SMD 68K OHM 5% 1/16W 0402; DIGI-KEY PART NO: 311-68KJRCT-ND; MFG Part number: RC0402JR-0768KL; Manufacturer: Yageo; Mfr_Name: Yageo; Mfr_Part#: RC0402JR-0768KL; Price: 0.10
R51 = 330_ohm_5%_0805_0: RES SMD 36K OHM 1% 1/16W 0402; MFG Part number: RC0402FR-0736KL; Manufacturer: Yageo; Mfr_Name: Yageo; Mfr_Part#: RC0402FR-0736KL
R53 = Resistor_402_Generic_SMD: RES SMD 0 OHM JUMPER 1/10W 0402; ALTERNATE PART NUMBER: ERJ-2GE0R00X; Alternate Manufacturer: Panasonic Electronic Components; Alternate Mfr Part #: RC0402JR-070RL; MFG Part number: MCS04020Z0000ZE000; Manufacturer: Vishay Beyschlag; Mfr_Name: Vishay Beyschlag; Mfr_Part#: MCS04020Z0000ZE000
R72 R80 = Resistor_402_Generic_SMD: RES SMD 0.01 OHM 1% 1W 1206; MFG Part number: ERJ-8CWFR010V; Manufacturer: Panasonic Electronic Components; Mfr_Name: Panasonic Electronic Components; Mfr_Part#: ERJ-8CWFR010V
R76 R77 = 330_ohm_5%_0805_0: RES SMD 2.2 OHM 5% 1/10W 0603; MFG Part number: ERJ-3GEYJ2R2V; Manufacturer: Panasonic Electronic Components; Mfr_Name: Panasonic Electronic Components; Mfr_Part#: ERJ-3GEYJ2R2V
R84 = Y14870R00500B9R_1: RES SMD 0.005 OHM 1% 2W 2512; MFG Part number: CSNL2512FT5L00; Manufacturer: Stackpole Electronics Inc.; Mfr_Name: Stackpole Electronics Inc.; Mfr_Part#: CSNL2512FT5L00; Package: 2512; Tolerance: 1%; Wattage: 2W
R85 R106 = 330_ohm_5%_0805_0: RES SMD 0 OHM JUMPER 1/10W 0402; ALTERNATE PART NUMBER: ERJ-2GE0R00X; Alternate Manufacturer: Panasonic Electronic Components; Alternate Mfr Part #: RC0402JR-070RL; MFG Part number: MCS04020Z0000ZE000; Manufacturer: Vishay Beyschlag; Mfr_Name: Vishay Beyschlag; Mfr_Part#: MCS04020Z0000ZE000
R87 = 330_ohm_5%_0805_0: RES SMD 10K OHM 1% 1/16W 0402; MFG Part number: RC0402FR-0710KL; Manufacturer: Yageo; Mfr_Name: Yageo; Mfr_Part#: RC0402FR-0710KL; Mfr_Part_Number: ERJ-2GEJ473X; Tolerance: 1%
R88 = 5.49K-1_10W-1%-0603: RES SMD 200K OHM 5% 1/10W 0402; Dist1_PN: P1.00KHTR-ND; MFG Part number: ERJ-2GEJ204X; Manufacturer: Panasonic Electronic Components; Mfg1_PN: RC0402JR-07150KL; Mfr_Name: Panasonic Electronic Components; Mfr_Part#: ERJ-2GEJ204X; PART_NUMBER: RC0402JR-07150KL; Tolerance: 5%
R107 = 330_ohm_5%_0805_0: RES SMD 51K OHM 1% 1/16W 0402; MFG Part number: RC0402FR-0751KL; Manufacturer: Yageo; Mfr_Name: Yageo; Mfr_Part#: RC0402FR-0751KL; Mfr_Part_Number: ERJ-2GEJ473X; Tolerance: 1%
U1 = SC8802_2: SYNCHRONOUS 4-WAY BIDIRECTIONAL BUCK-BOOST CHARGE-DISCHARGE CONTROLLER; Manufacturer: SouthChip; Mfr_Name: SouthChip

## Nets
GND: C1.1 C1.2 C2.1 C2.2 C3.1 C3.2 C3#2.2 C4.1 C4.2 C5.1 C5.2 C6.1 C6.2 C7.1 C8.1 C8.2 C9.1 C9.2 C10.1 C10.2 C11.2 C11#2.1 C11#2.2 C16.1 C16.2 C17.1 C17.2 C18.1 C18.2 C19.1 C19.2 C21.2 C22.1 C22.2 C23.1 C25.1 C30.2 C32.2 C37.2 C42.1 C43.1 C43.2 C44.1 C44.2 C45.2 C46.2 C47.2 C56.2 C57.1 C57.2 C58.1 C58.2 C59.1 C59.2 C60.1 C60.2 C61.1 C61.2 C62.1 C62.2 C65.2 C66.2 C73.1 C73.2 C74.1 C74.2 C75.1 C75.2 C76.1 C76.2 C77.1 C77.2 C78.1 C78.2 C79.2 C82.1 C82.2 C83.1 C83.2 C86.1 C86.2 D1.A(ANODE) D1.C(CATHODE) D2.C(CATHODE) D4.A D8.A J1.1 J1.2 J2.2 J3.2 J3.3 J5.2 J10.A4(VBUS_1) J10.A6(D+) J10.A9(VBUS_2) J10.B4(VBUS_3) J10.B5(CC2) J10.B6(D+) J10.B9(VBUS_4) L2.2 NT1.2 Q1.1(S2) Q1.3(S1) Q1.7(D2) Q1.8(D2) Q2.2(G2) Q2.4(G1) Q2.5(D1) Q2.6(D1) Q2.7(D2) Q2.8(D2) Q6.1(S1) Q6.2(S2) Q6.3(S3) Q7.1(S1) Q7.2(S2) Q7.3(S3) Q7.5(D1) Q7.6(D2) Q7.7(D3) Q7.8(D4) Q10.1(S1) Q10.2(S2) Q10.3(S3) R1#2.1 R2.2 R3.1 R4.1 R5.1 R5.2 R6.2 R7.2 R8.1 R9.1 R9.2 R10.2 R12.1 R12.2 R13.2 R14.1 R15.2 R17.2 R20.1 R21.2 R34.2 R39.2 R47.1 R48.2 R50.1 R51.1 R53.1 R58.1(A) R59.2 R72.2 R76.1 R80.2 R84.2 R106.2 R107.2 TP1.1 TP2.1 TP3.1 TP3#2.1 TP4.1 TP5.1 TP6.1 TP8.1 TP10.1 TP14.1 U1.9(CSEL) U1.14(AGND) U1.17(SNS2N) U1.18(SNS2P) U1.19(VBAT) U1.21(HD2) U1.22(SW2) U1.23(LD2) U1.24(VCC) U1.25(PGND) U1.30(VBUS) U1.33(EPAD) U4.2(VIN) U4.4(PS/SYNC) U4.7(GND) U4.11(PGND)
VBUS_C: C7.2 J5.1 Q1.5(D1) Q1.6(D1) TP7.1
VDDD: R40.1 R89.1 R91.1 R93.1 R109.1
8802_EN: R40.2 R89.2 R93.2 U1.1(CE) U1.2(DIR) U1.5(IPWM)
8802_FB: C23.2 D4.K R85.2 TP18.1 U1.20(BT2)
C_CTRL: R1.2 R109.2 U1.4(PG)
CC1: C21.1 C30.1 J10.A5(CC1) R25.1 TP11.1 U1.15(COMP)
D-: J10.A7(D-) J10.B7(D-) R17.1 R21.1 U1.16(FB2)
FB1_88: R85.1 R87.1 R88.2 U1.13(FB1)
HD1_88: R78.2 U1.28(HD1)
ILIM1_88: C37.1 R20.2 R39.1 U1.11(ILIM1)
ILIM2_88: C32.1 R35.1 U1.12(ILIM2)
ITUNE: R35.2 U1.6(ITUNE)
LD1_88: R19.2 U1.26(LD1)
P2.1: R50.2 U1.10(FREQ)
P_CTRL_FET: R8.2 R91.2 U1.3(PWM)
RETURN_GND: C11.1 C13.2 D2.A(ANODE) J3.1 J10.A1(GND_1) J10.A12(GND_2) J10.B1(GND_3) J10.B12(GND_4) NT1.1 R11.2 R84.1
SNS2P_88: C56.1 Q6.5(D1) Q6.6(D2) Q6.7(D3) Q6.8(D4) R10.1 R72.1
SW1_88: C27.2 L2.1 Q10.5(D1) Q10.6(D2) Q10.7(D3) Q10.8(D4) Q11.1(S1) Q11.2(S2) Q11.3(S3) R77.1 U1.27(SW1)
SWD_CLK/P0.1: J1.4 R53.2 U1.8(DT)
SWD_IO/P0.0: J1.5 R48.1 R51.2 U1.7(VINREG)
N17067555: Q2.1(S2) Q2.3(S1) R7.1
N17067599: C3#2.1 Q1.2(G2) Q1.4(G1) R1.1 R2.1 R3.2 R4.2
N17086653: C66.1 R77.2
N17086665: Q6.4(G) R6.1
N17086831: Q7.4(G) R13.1
N17086918: C79.1 Q11.5(D1) Q11.6(D2) Q11.7(D3) Q11.8(D4) R31.2 R80.1
N17087706: Q10.4(G) R19.1
N17087908: C25.2 R25.2
N17088006: C34.2 R31.1 U1.31(SNS1N)
N17088008: C34.1 R34.1 U1.32(SNS1P)
N17088037: C27.1 D8.K U1.29(BT1)
N17088067: C65.1 R76.2
N17093134: C13.1 J10.SH_1(SH1) J10.SH_2(SH2) J10.SH_3(SH3) J10.SH_4(SH4) J10.SH_5(SH5) J10.SH_6(SH6) R11.1
N17160162: Q11.4(G) R78.1
N17223061: R14.2 R15.1
N17264482: D3.C(CATHODE) R1#2.2
N17480405: L4.2 U4.10(L2)
N17480407: L4.1 U4.1(L1)
N17480415: C45.1 C46.1 C47.1 R54.2 R57.1 R60.2(B) TP4#2.1 U4.9(VOUT)
N17492074: R88.1 R106.1
N17492077: R87.2 R107.1
N17494926: R59.1 TP15.1 U4.3(EN)
N17500848: C42.2 U4.6(VAUX)
N17503326: R58.2(B) R60.1(A) U4.8(FB)
N17504242: R57.2 TP13.1 U4.5(PG)
N17604879: D3.A(ANODE) J2.1
N17605748: R47.2 R54.1

Not connected (* = marked no-connect by the designer): J1 3*; J10 A2(TX1+)* A3(TX1-)* A8(SBU1)* A10(RX2-)* A11(RX2+)* B2(TX2+)* B3(TX2-)* B8(SBU2)* B10(RX1-)* B11(RX1+)*

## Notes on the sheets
sheet 1
- SC8802 REGULATOR
- 5A  (Max)
- 5A (Max)
- Default 5V   OUTPUT
sheet 2
- INPUT CIRCUIT
- DC INPUT
  12V Max / 5A
- 5A Max
- COLOUR: BLUE
- DC JACK
  12V / 4.2A
- VDDD POWER
sheet 3
- REVISION HISTORY
- REV
- DESCRIPTION OF CHANGE
- DATE
- 01
- INITIAL RELEASE
- 2026/03/16
sheet 4
- PMG1-S0 DRP Reference Design
- CONTENTS
- PAGE
- DESCRIPTION
- 01
- TITLE & TABLE OF CONTENTS
- 02
- PMG1-S0 CONTROLLER
- 03
- PROVIDER & CONSUMER PATH
- 04
- INPUT & STEP DOWN REGULATOR
- 05
- SC8802 REGULATOR
- 06
- REVISION HISTORY
sheet 5
- PMG1-S0 CONTROLLER
- PROGRAMMER
sheet 6
- TYPE-C CONNECTOR
- PROVIDER PATH
- CONSUMER PATH
- LOAD TERMINAL
- 5A Max
- Terminals provided to
   test 5A loading on the
  Type-C regulator
- COLOUR: GREEN
